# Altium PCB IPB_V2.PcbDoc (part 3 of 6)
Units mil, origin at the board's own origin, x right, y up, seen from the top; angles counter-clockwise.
Board outline 14000 x 12000 mil, 6 copper layers (Top, L2 - Plane/Horiz, L3 - Horiz, L4 - Vert, L5 - Plane/Horiz, Bottom), stack 61.468 mil thick; 657 components, 436 nets, 1897 pads, 873 vias.
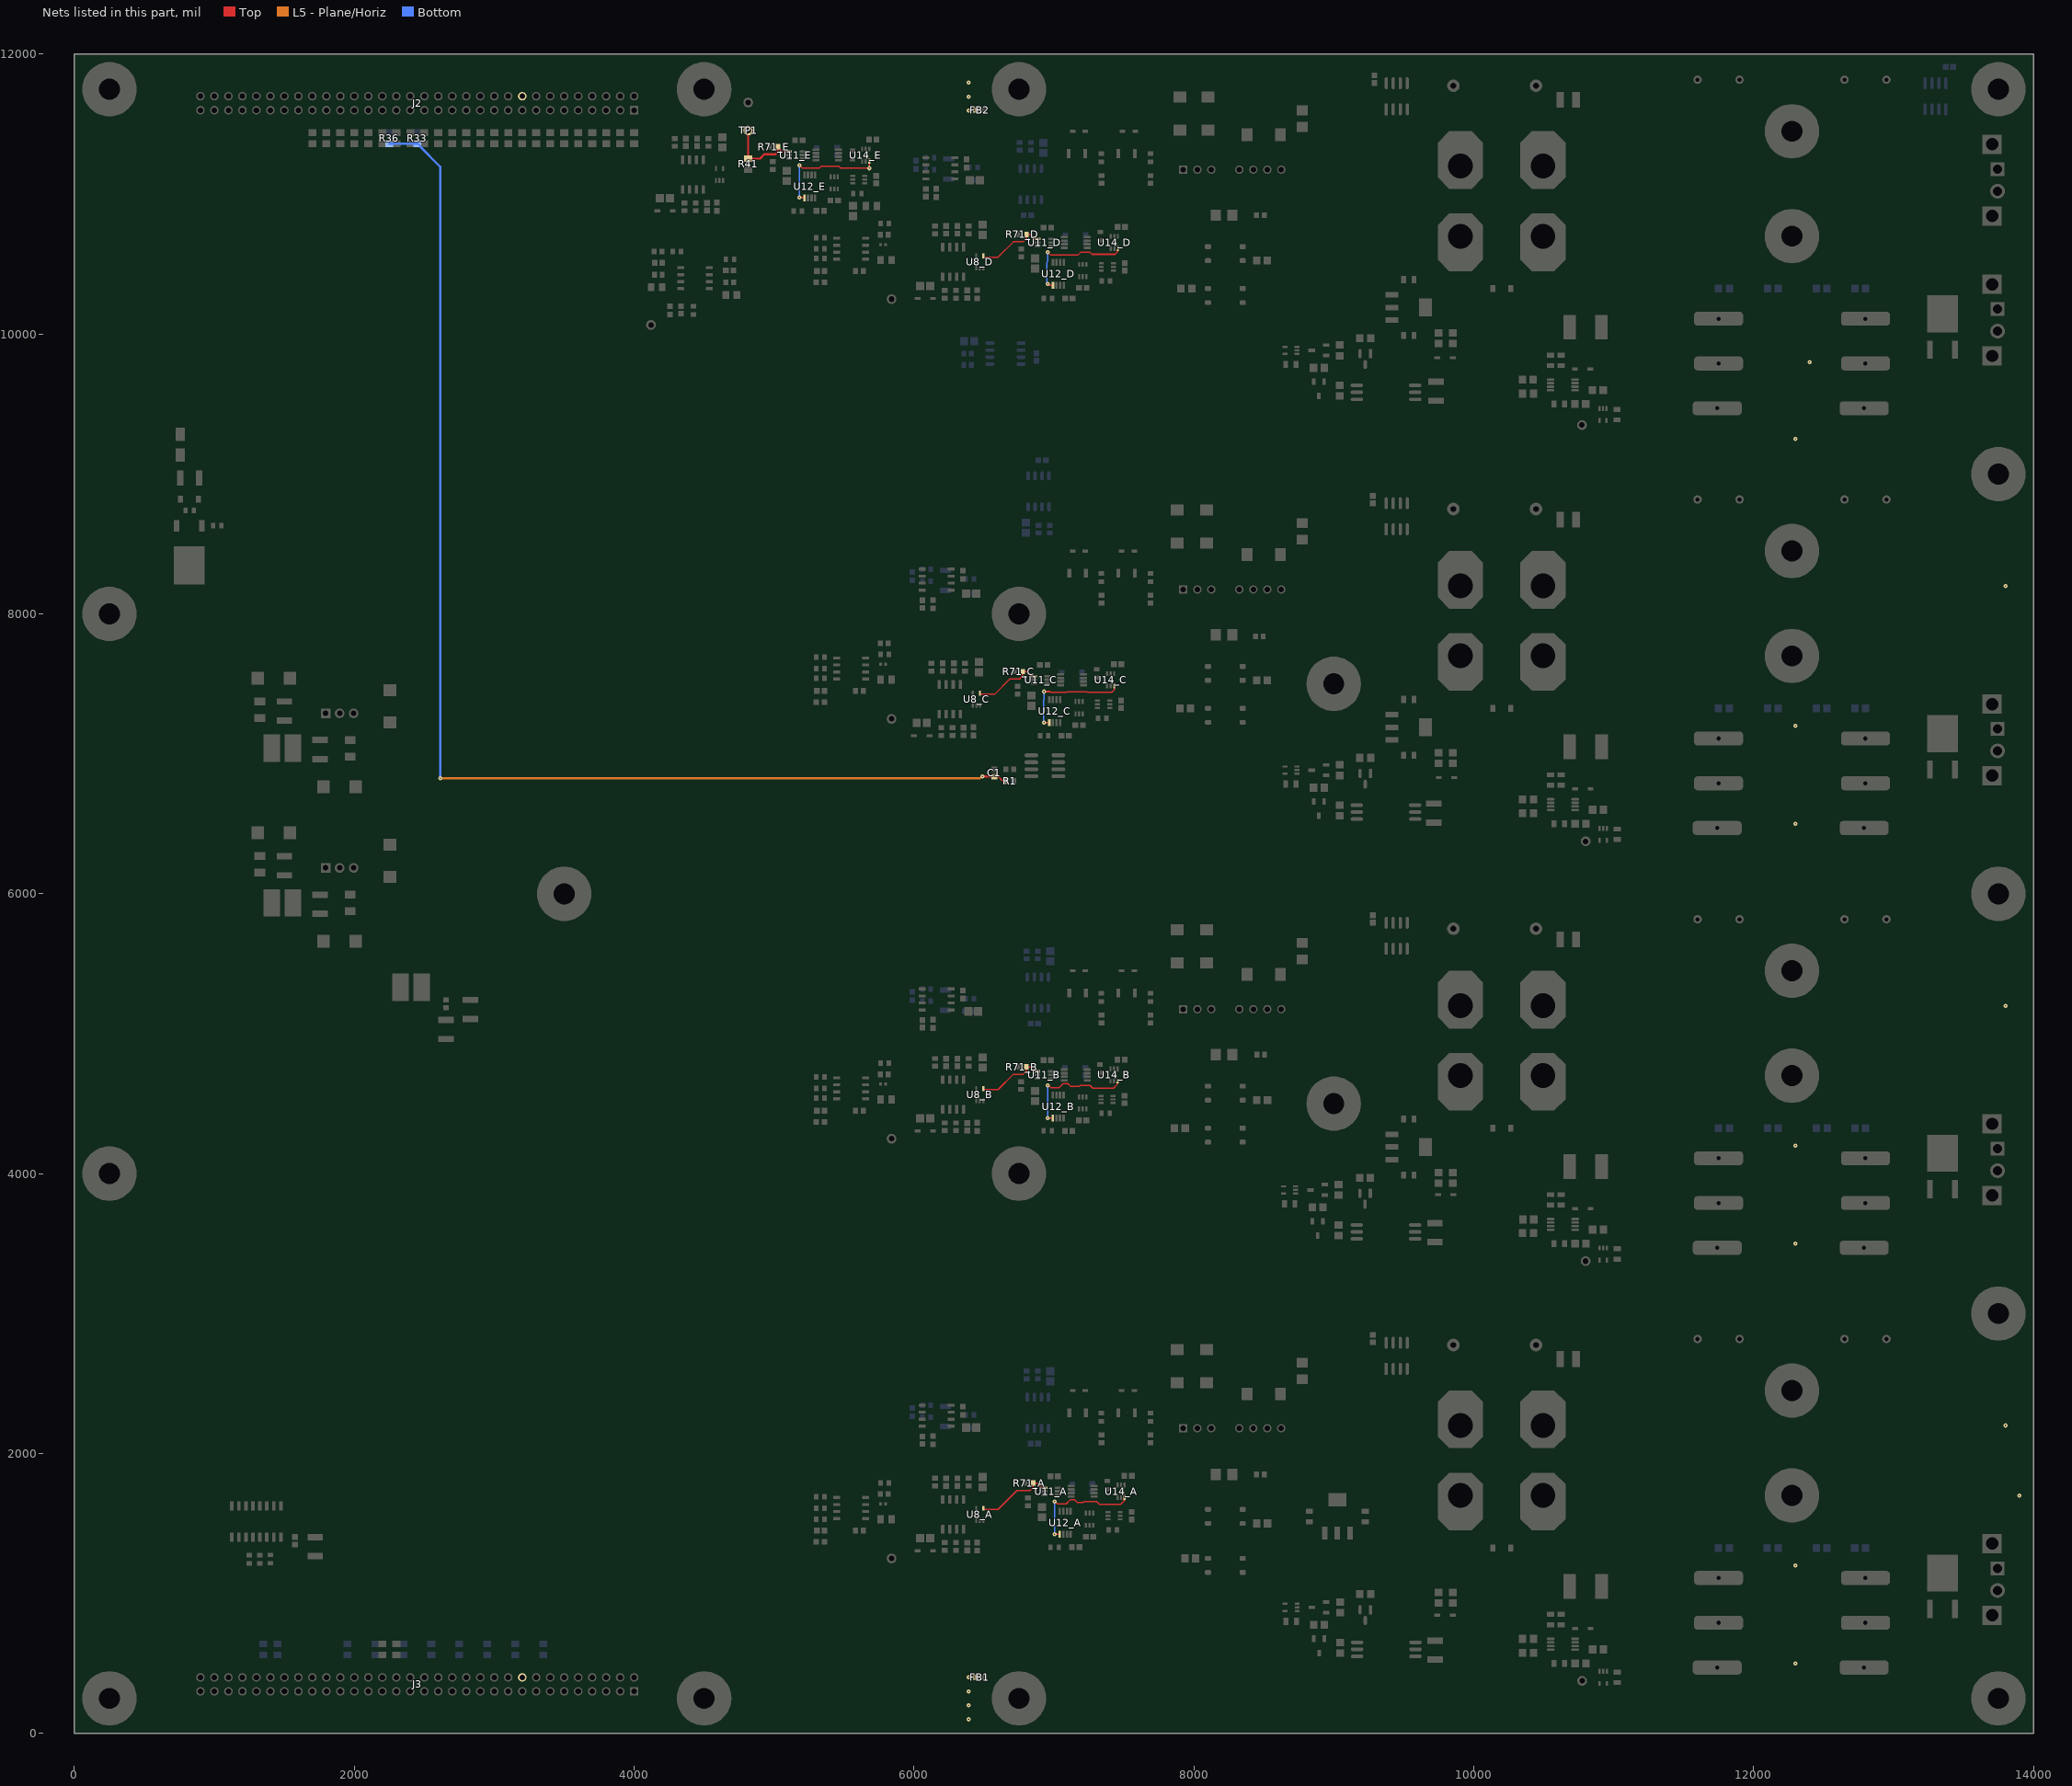
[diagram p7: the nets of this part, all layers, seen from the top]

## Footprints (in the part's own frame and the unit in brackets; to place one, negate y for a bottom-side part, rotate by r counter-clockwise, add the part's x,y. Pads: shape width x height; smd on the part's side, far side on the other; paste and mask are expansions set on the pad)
ADI-R-8_M [mm] "SOIC, 8-Leads, Body 4.9x3.9mm, Pitch 1.27mm, IPC Low Density"
  oval 2.5x0.7 smd: 1(-2.45,1.905) 2(-2.45,0.635) 3(-2.45,-0.635) 4(-2.45,-1.905) 5(2.45,-1.905) 6(2.45,-0.635) 7(2.45,0.635) 8(2.45,1.905)
  silkscreen extent -2.57,-2.5 0.8,2.93, body extent -2,-2.5 2,2.5, height 1.75
CAPC0402(1005)33_L [mm] "Chip Capacitor, Body 1.0x0.5mm, Height 0.33mm, IPC High Density"
  rrect25% 0.5x0.55 smd: 1(-0.45,0) 2(0.45,0)
  silkscreen extent 0,-0.2 0,0.2, body extent -0.5,-0.25 0.5,0.25, height 0.55
CAPC1608X90X40ML10T20 [mm] "Chip Capacitor, 2-Leads, Body 1.70x0.90mm, IPC Low Density"
  rect 1.05x1.05 smd: 1(-0.675,0) 2(0.675,0)
  body extent -0.85,-0.45 0.85,0.45, height 0.9
CAPC1608X94X35NL15T15 [mm] "Chip Capacitor, 2-Leads, Body 1.75x0.96mm, IPC Medium Density"
  rect 1.05x1 smd: 1(-0.75,0) 2(0.75,0)
  body extent -0.87,-0.48 0.87,0.48, height 0.94
CAPC2012X11M [mm] "Chip Capacitor, 2-Leads, Body 2.00x1.25mm, IPC Low Density"
  rect 1.5x1.55 smd: 1(-0.9,0) 2(0.9,0)
  body extent -1.1,-0.72 1.1,0.72, height 1.1
CAPC2013X95X50ML10T25 [mm] "Chip Capacitor, 2-Leads, Body 2.10x1.35mm, IPC Low Density"
  rect 1.45x1.5 smd: 1(-0.925,0) 2(0.925,0)
  body extent -1.05,-0.67 1.05,0.67, height 0.95
CAPC3225X270X30ML30 [mm] "Chip Capacitor, 2-Leads, Body 3.5x2.7mm, IPC Low Density"
  rect 1.15x2.8 smd: 1(-1.725,0) 2(1.725,0)
  silkscreen extent -0.75,-1.3 0.75,1.3, body extent -1.75,-1.35 1.75,1.35, height 2.7
CONV_RS3-2412S [mm]
  rect 1.508x1.508 hole 1: 1(-8.9,1.4)
  round 1.508 hole 1: 2(-6.36,1.4) 3(-3.82,1.4) 5(1.26,1.4) 6(3.8,1.4) 7(6.34,1.4) 8(8.88,1.4)
  silkscreen extent -11.9,-4.6 10.9,4.6, body extent -10.9,-4.6 10.9,4.6, height 11.1
D0008A_L [mm] "SOIC, 8-Leads, Body 5x4mm, Pitch 1.27mm, IPC High Density"
  rrect18% 1.25x0.55 smd: 1(-2.625,1.905) 2(-2.625,0.635) 3(-2.625,-0.635) 4(-2.625,-1.905) 5(2.625,-1.905) 6(2.625,-0.635) 7(2.625,0.635) 8(2.625,1.905)
  silkscreen extent -2.75,-2.5 1.6,2.85, body extent -3,-2.45 3,2.45, height 1.63
D0016A_M [mm] "SOIC, 16-Leads, Body 10x4mm, Pitch 1.27mm, IPC Low Density"
  rrect15% 1.65x0.65 smd: 1(-2.825,4.445) 2(-2.825,3.175) 3(-2.825,1.905) 4(-2.825,0.635) 5(-2.825,-0.635) 6(-2.825,-1.905) 7(-2.825,-3.175) 8(-2.825,-4.445) 9(2.825,-4.445) 10(2.825,-3.175) 11(2.825,-1.905) 12(2.825,-0.635) 13(2.825,0.635) 14(2.825,1.905) 15(2.825,3.175) 16(2.825,4.445)
  silkscreen extent -2.95,-5 1.6,5.45, body extent -3,-4.95 3,4.95, height 1.59
DCK0006A_M [mm] "SOT23, 6-Leads, Body 2.15x1.4mm, Pitch 0.65mm, IPC Low Density"
  rrect22% 1.05x0.45 smd: 1(-1.225,0.65) 2(-1.225,0) 3(-1.225,-0.65) 4(1.225,-0.65) 5(1.225,0) 6(1.225,0.65)
  silkscreen extent -1.35,-1.1 0.3,1.55, body extent -1.14,-1 1.14,1, height 0.94
DCT0008A_M [mm] "SOP, 8-Leads, Body 2.9x3.2mm, Pitch 0.65mm, IPC Low Density"
  rrect22% 1.25x0.45 smd: 1(-2.075,0.975) 2(-2.075,0.325) 3(-2.075,-0.325) 4(-2.075,-0.975) 5(2.075,-0.975) 6(2.075,-0.325) 7(2.075,0.325) 8(2.075,0.975)
  silkscreen extent -2.2,-1.6 1.05,1.87, body extent -2.01,-1.47 2.01,1.48, height 1.3
DIOM4326X11M [mm] "Molded Diode, 2-Leads, Body 4.30x2.60mm, IPC Low Density"
  rect 2.45x1.7 smd: 1(-1.875,0) 2(1.875,0)
  silkscreen extent -2.3,-1.4 3.07,1.53, body extent -2.52,-1.4 2.52,1.4, height 1.1
FAIR-SOD-323_V [mm] "SODFL, 2-Leads, Body 1.25x1.7mm"
  rect 1.05x0.55 smd: 1(-1.4,0) 2(1.4,0)
  silkscreen extent -0.85,-0.63 2.43,0.63, body extent -1.25,-0.63 1.25,0.63, height 1
FP-BLM18-0_15-t0_5-d1_2-IPC_B [mil]
  rect 43.55x37.73 smd paste+0 mask+0: 1(-26.62,0) 2(26.62,0)
  silkscreen extent -48,-35 48,35, body extent -58,-29 58,29, height 10
FP-C1206X102KGRACAUTO-IPC_A [mil]
  rect 70.97x80.85 smd paste+0 mask+0: 1(-59.06,0) 2(59.06,0)
  body extent -114,-60 114,60, height 10
FP-CGA5L-0_3-0_1-IPC_A [mm]
  rect 0.956x2.006 smd paste+0 mask+0: 1(-1.825,0) 2(1.825,0)
  silkscreen extent -1.05,-1 1.05,1, body extent -1.6,-0.76 1.6,0.84, height 1.9
FP-D0008A-IPC_B [mil]
  rect 85.4x22.92 smd paste+0 mask+0: 1(-93.06,75)
  rrect100% 85.4x22.92 smd paste+0 mask+0: 2(-93.06,25) 3(-93.06,-25) 4(-93.06,-75) 5(93.06,-75) 6(93.06,-25) 7(93.06,25) 8(93.06,75)
  silkscreen extent -162,-97 31,97, body extent -146,-106 146,106, height 10
FP-D0008A-MFG [mm] "SOIC, 8-Leads, Body 5x4mm, Pitch 1.27mm, IPC High Density"
  rrect17% 1.55x0.6 smd paste+0 mask+0: 1(-2.7,1.905) 2(-2.7,0.635) 3(-2.7,-0.635) 4(-2.7,-1.905) 5(2.7,-1.905) 6(2.7,-0.635) 7(2.7,0.635) 8(2.7,1.905)
  silkscreen extent -4.17,-2.5 1.5,2.5, body extent -3.57,-2.75 3.57,2.75, height 0.25
FP-DCK0005A-MFG [mm]
  rect 0.9x0.4 smd paste-1000 mask+0: 1(-1.1,0.65) 2(-1.1,0) 3(-1.1,-0.65) 4(1.1,-0.65) 5(1.1,0.65)
  silkscreen extent -2.22,-1.07 0.7,1.07, body extent -1.65,-1.33 1.65,1.33, height 0.25
FP-DCK0006A-MFG [mm]
  rect 0.9x0.4 smd paste-1000 mask+0: 1(-1.1,0.65) 2(-1.1,0) 3(-1.1,-0.65) 4(1.1,-0.65) 5(1.1,0) 6(1.1,0.65)
  silkscreen extent -2.22,-1.07 0.27,1.07, body extent -1.65,-1.33 1.65,1.33, height 0.25
FP-M80-5000000M5-02-333-0-MFG [mm]
  rect 2.5x2.5 hole 1.65 paste-2539.97 mask+0: A(2,1.8)
  round 2.667 hole 1.65 paste-2539.97 mask+0: B(-2,1.8)
  rect 3.5x3.5 hole 2.25 paste-2539.97 mask+0: MT1(-6.5,2.8) MT2(6.5,2.8)
  silkscreen extent -9.25,-4.4 9.25,5.2, body extent -9.35,-4.5 9.35,4.6, height 0.25
FP-SOT23-IPC_A [mm]
  rect 1.655x0.602 smd paste+0 mask+0: 1(-0.975,0.95)
  rrect100% 1.655x0.602 smd paste+0 mask+0: 2(-0.975,-0.95) 3(0.975,0)
  silkscreen extent 0,-1.45 0.65,1.45, body extent -2.3,-1.95 2.3,1.95, height 0.25
FP-T491X226K050AT-MFG [mm]
  rect 1.99x2.33 smd paste+0 mask+0: 1(-3.01,0) 2(3.01,0)
  silkscreen extent -3.8,-2.3 5.28,2.3, body extent -3.65,-2.15 3.65,2.15, height 4.3
G41C [mil] "5kV SPDT High Voltage Relay"
  rrect50% 350x100 hole 30 slot 200 at 0 deg: 1(0,390) 3(10,1030) 4(0,710)
  round 60 hole 30: 2(-150,-1318) 5(150,-1318)
  body extent -325,-1655 325,1109, height 690
INA310 [mm] "INA310 Current Sense Amp."
  oval 1.4x0.45 smd: 1(-2.225,0.975) 2(-2.225,0.325) 3(-2.225,-0.325) 4(-2.225,-0.975) 5(2.225,-0.975) 6(2.225,-0.325) 7(2.225,0.325) 8(2.225,0.975)
  silkscreen extent -2.35,-1.55 1.15,1.9, body extent -2.45,-1.55 2.45,1.55, height 1.1
INDP4848X30M [mm] "Precision Wire Wound Inductor, 2-Leads, Body 4.80x4.80mm, IPC Low Density"
  rect 3x5 smd: 1(-1.9,0) 2(1.9,0)
  body extent -2.4,-2.4 2.4,2.4, height 2.8
INF-PG-TO252-3-1_M [mm] "DPAK, 3-Leads, Body 6.525x6.12mm, Pitch 2.28mm, IPC Low Density"
  rect 2.05x1 smd: 1(-4.8,2.28) 3(-4.8,-2.28)
  rect 6.9x5.65 smd: 2(2.4,0)
  silkscreen extent -4.92,-3.35 -1.45,3.46, body extent -2.05,-3.32 4.17,3.32, height 2.35
IXFN66N85X-Footprint-1 [mil]
  oct 325x412.5 hole 177.2 copper offset 0,43.75: D(-295,250) S2(295,250)
  oct 325x412.5 hole 177.2 copper offset 0,-43.75: G(-295,-250) S1(295,-250)
  silkscreen extent -750,-525 750,525, body extent -749,-490 751,490, height 473
KEMT-D-7343-31-2_L [mm] "Molded TAN Capacitor, 2-Leads, Body 7.6x4.6mm, IPC High Density"
  rect 2.2x2.35 smd: 1(-2.925,0) 2(2.925,0)
  silkscreen extent -4.53,-2.3 3.8,2.3, body extent -3.8,-2.3 3.8,2.3, height 3.1
"Keystone 5001" [mil]
  round 70 hole 40: 1(0,0)
  silkscreen extent -55,-55 55,55, body extent -50,-50 50,50, height 180
"Keystone 5002" [mil]
  round 70 hole 40: 1(0,0)
  silkscreen extent -55,-55 55,55, body extent -50,-50 50,50, height 180
"MH-M3-Footprint-1 - Oversized MARS2" [mil] "Oversized specific for the MARS2 Project."
  round 390 / inner round 200 / far side round 390 hole 150: 1(0,0)
ONSC-SOD-123-2-425-04_V [mm] "SOD, 2-Leads, Body 2.69x1.6mm"
  rect 0.91x1.22 smd: 1(-1.635,0) 2(1.635,0)
  silkscreen extent -1.76,-0.8 0.78,1.28, body extent -1.35,-0.8 1.35,0.8, height 1.35
PANASONIC_ERJ6E [mm] "PANASONIC ERJ6E series 0805 resistors. /  / Chip Resistor, 2-Leads, Body 2.00x1.25mm, IPC Low Density"
  rect 1.35x1.45 smd: 1(-0.975,0) 2(0.975,0)
  body extent -1.1,-0.67 1.1,0.67, height 0.7
R76QI222050H4J-Footprint-1 [mil]
  round 90 hole 41.34: 1(-295.28,0) 2(295.28,0)
  silkscreen extent -375,-150 375,150, body extent -360,-122 360,122, height 476
REPO-R-78XX-3_V [mm] "Module, 3-Leads, Body 11.5x7.55mm, Pitch 2.54mm"
  rect 1.75x1.75 hole 1: 1(-2.54,0)
  round 1.75 hole 1: 2(0,0) 3(2.54,0)
  silkscreen extent -5.75,-2.77 5.75,5.55, body extent -5.75,-2 5.75,5.55, height 10.2
RESC1608X55X25ML10T15 [mm] "Chip Resistor, 2-Leads, Body 1.70x0.90mm, IPC Low Density"
  rect 0.8x1 smd: 1(-0.75,0) 2(0.75,0)
  body extent -0.85,-0.45 0.85,0.45, height 0.55
RESC1609X50X30ML08T20 [mm] "Chip Resistor, 2-Leads, Body 1.65x0.95mm, IPC Low Density"
  rect 0.9x1.05 smd: 1(-0.7,0) 2(0.7,0)
  body extent -0.82,-0.48 0.82,0.48, height 0.5
RESC2013X60X35ML10T20 [mm] "Chip Resistor, 2-Leads, Body 2.1x1.35mm, IPC Low Density"
  rect 1.2x1.45 smd: 1(-1,0) 2(1,0)
  silkscreen extent -0.1,-0.62 0.1,0.62, body extent -1.05,-0.68 1.05,0.67, height 0.6
RESC3115X07M [mm] "Chip Resistor, 2-Leads, Body 3.13x1.55mm, IPC Low Density"
  rect 1.4x1.95 smd: 1(-1.5,0) 2(1.5,0)
  silkscreen extent -0.4,-0.87 0.4,0.87, body extent -1.63,-0.72 1.63,0.72, height 0.7
RESC3126X06M [mm] "Chip Resistor, 2-Leads, Body 3.10x2.60mm, IPC Low Density"
  rect 1.4x2.85 smd: 1(-1.45,0) 2(1.45,0)
  silkscreen extent -0.35,-1.32 0.35,1.33, body extent -1.6,-1.38 1.6,1.38, height 0.65
RESC7142X88N [mm]
  rect 2.28x4.47 smd: 1(-2.895,0) 2(2.895,0)
  silkscreen extent -1.44,-2.1 1.44,2.1, body extent -3.56,-2.1 3.56,2.1, height 0.89
SMTC-ESQ-132-14-X-D [mm] "Elevated Socket, 2x32 Pins, Vertical, 2.54mm Pitch, Female"
  rect 1.55x1.55 hole 1.02: 1(0,0)
  round 1.55 hole 1.02: 2(0,-2.54) 3(2.54,0) 4(2.54,-2.54) 5(5.08,0) 6(5.08,-2.54) 7(7.62,0) 8(7.62,-2.54) 9(10.16,0) 10(10.16,-2.54) 11(12.7,0) 12(12.7,-2.54) 13(15.24,0) 14(15.24,-2.54) 15(17.78,0) 16(17.78,-2.54) 17(20.32,0) 18(20.32,-2.54) 19(22.86,0) 20(22.86,-2.54) 21(25.4,0) 22(25.4,-2.54) 23(27.94,0) 24(27.94,-2.54) 25(30.48,0) 26(30.48,-2.54) 27(33.02,0) 28(33.02,-2.54) 29(35.56,0) 30(35.56,-2.54) 31(38.1,0) 32(38.1,-2.54) 33(40.64,0) 34(40.64,-2.54) 35(43.18,0) 36(43.18,-2.54) 37(45.72,0) 38(45.72,-2.54) 39(48.26,0) 40(48.26,-2.54) 41(50.8,0) 42(50.8,-2.54) 43(53.34,0) 44(53.34,-2.54) 45(55.88,0) 46(55.88,-2.54) 47(58.42,0) 48(58.42,-2.54) 49(60.96,0) 50(60.96,-2.54) 51(63.5,0) 52(63.5,-2.54) 53(66.04,0) 54(66.04,-2.54) 55(68.58,0) 56(68.58,-2.54) 57(71.12,0) 58(71.12,-2.54) 59(73.66,0) 60(73.66,-2.54) 61(76.2,0) 62(76.2,-2.54) 63(78.74,0) 64(78.74,-2.54)
  silkscreen extent -1.53,-3.74 80.27,1.2, body extent -1.52,-3.81 80.26,1.27, height 11.05
SODFL250X80-2M [mm] "SODFL, 2-Leads, Body 1.25x2.50mm, IPC Low Density"
  rect 1x0.55 smd: 1(-1.15,0) 2(1.15,0)
  silkscreen extent -1.6,-0.7 0.9,0.7, body extent -1.25,-0.67 1.25,0.67, height 0.8
SOIC127P600X175-8M [mm] "SOIC, 8-Leads, Body 4.90x3.90mm, Pitch 1.27mm, IPC Low Density"
  oval 1.65x0.65 smd: 1(-2.825,1.905) 2(-2.825,0.635) 3(-2.825,-0.635) 4(-2.825,-1.905) 5(2.825,-1.905) 6(2.825,-0.635) 7(2.825,0.635) 8(2.825,1.905)
  silkscreen extent -2.95,-2.5 1.6,2.91, body extent -3,-2.5 3,2.5, height 1.75
SOIC127P1150X355-6M [mm] "SOIC, 6-Leads, Body 4.68x7.50mm, Pitch 1.27mm, IPC Low Density"
  oval 2.25x0.65 smd: 1(-5.3,1.27) 2(-5.3,0) 3(-5.3,-1.27) 4(5.3,-1.27) 5(5.3,0) 6(5.3,1.27)
  silkscreen extent -5.42,-2.4 3.78,2.4, body extent -5.75,-2.4 5.75,2.4, height 3.55
SOT89-150P341X160-3M [mm] "SOT89, 3-Leads, Body 4.50x2.45mm, Pitch 1.50mm, Lead Span 3.4mm, IPC Low Density"
  rect 1.6x0.7 smd: 1(-1.65,1.5) 3(-1.65,-1.5)
  round 0.025 smd: 2(-1.7,0)
  Top region: -0.95,0.35 -0.3,1 -0.3,1 1.8,1 2.45,0.35 2.45,-0.35 1.8,-1 -0.3,-1 -0.95,-0.35 -2.45,-0.35 -2.45,0.35
  silkscreen extent -1.93,-2.3 1.45,2.53, body extent -2.2,-2.3 1.85,2.3, height 1.6
SOT95P237X111-3M [mm] "SOT23, 3-Leads, Body 2.92x2.37mm, Pitch 0.95mm, IPC Low Density"
  rect 1.2x0.65 smd: 1(-1.3,0.95) 2(-1.3,-0.95) 3(1.3,0)
  silkscreen extent -1.42,-1.5 0.7,1.95, body extent -1.32,-1.52 1.32,1.52, height 1.11
SOT230P700X180-4M [mm] "SOT223, 4-Leads, Body 6.50x7.00mm (avg), Pitch 2.30mm, IPC Low Density"
  rect 2.35x1 smd: 1(-3.025,2.3) 2(-3.025,0) 3(-3.025,-2.3)
  rect 2.35x3.25 smd: 4(3.025,0)
  silkscreen extent -3.15,-3.35 1.4,3.47, body extent -3.5,-3.35 3.5,3.35, height 1.8
TO-252AA-IPC_A-APL [mm] "IPC Level A, Low-Density, DPAK. Created via JEDEC TO-252 dimensions and Altium IPC wizard."
  rect 3.3x1.05 smd: 1(-4.1,2.29) 3(-4.1,-2.29)
  rect 6.7x5.6 smd: 4(2.4,0)
  silkscreen extent -4.22,-3.35 -1.35,3.49, body extent -4.29,-3.37 5.61,3.37, height 2.52
WCAP-CSGP_0805_L2W1.25H0.8_Reflow [mm] "Ceramic Capacitors, body 2x1.25mm"
  rect 0.9x1.3 smd: 1(-0.95,0) 2(0.95,0)
  body extent -1,-0.62 1,0.63, height 0.8
WCAP-CSGP_0805_L2W1.25H1.25 [mm] "Ceramic Capacitors, body 2x1.25mm"
  rect 0.9x1.3 smd: 1(-0.95,0) 2(0.95,0)
  body extent -1,-0.63 1,0.63, height 1.25
WL-OCPT_SOP4 [mm] "Optocoupler Phototransistor, body 4.4x3.6mm"
  rrect50% 1.1x0.9 smd: 1(-3.15,1.27) 2(-3.15,-1.27) 3(3.15,-1.27) 4(3.15,1.27)
  silkscreen extent -3.27,-1.9 2.3,2.37, body extent -3.5,-1.8 3.5,1.8, height 2.1

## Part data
C1 C10_A C10_B C10_C C10_D C10_E C12 C29_A C29_B C29_C C29_D C29_E C30_A C30_B C30_C C30_D C30_E C31_A C31_B C31_C C31_D C31_E C32_A C32_B C32_C C32_D C32_E C34_A C34_B C34_C C34_D C34_E C35_A C35_B C35_C C35_D C35_E C57_A C57_B C57_C C57_D C57_E: library part CMP-001-00206-10, "Chip Capacitor, 100nF, +/- 10%, 50 V, X7R 0603 (1608 Metric)", Capacitance=100nF, Capacitor Type=Ceramic, Case/Package=0603, Dielectric=X7R, Max Operating Temperature=125°C, Min Operating Temperature=-55°C, Tolerance=10%, Voltage Rating=50V
C2 C25_A C25_B C25_C C25_D C25_E C27_A C27_B C27_C C27_D C27_E C28_A C28_B C28_C C28_D C28_E: library part CMP-001-00018-16, "Chip Capacitor, 100 nF, +/- 10%, 50 V, 0805 (2012 Metric)", Capacitance=100nF, Capacitor Type=Ceramic, Case/Package=0805, Max Operating Temperature=125°C, Min Operating Temperature=-55°C, Tolerance=10%, Voltage Rating=50V
C3 C6 C24_A C24_B C24_C C24_D C24_E C26_A C26_B C26_C C26_D C26_E: library part CMP-001-00153-10, "Chip Capacitor, 1nF, +/- 5%, 50 V, C0G 0603 (1608 Metric)", Capacitance=1nF, Capacitor Type=Ceramic, Case/Package=0603, Dielectric="C0G, NPO", Max Operating Temperature=125°C, Min Operating Temperature=-55°C, Tolerance=5%, Voltage Rating=50V
C4 C7_A C7_B C7_C C7_D C22_A C22_B C22_C C22_D C22_E C36_A C36_B C36_C C36_D: library part CMP-001-00166-10, "Chip Capacitor, 10nF, +/- 5%, 50 V, C0G 0603 (1608 Metric)", Capacitance=10nF, Capacitor Type=Ceramic, Case/Package=0603, Dielectric="C0G, NPO", Max Operating Temperature=125°C, Min Operating Temperature=-55°C, Tolerance=5%, Voltage Rating=50V
C5 C8_A C8_B C8_C C8_D C23_A C23_B C23_C C23_D C23_E C37_A C37_B C37_C C37_D C40_A C40_B C40_C C40_D C41_A C41_B C41_C C41_D: library part CMP-001-00003-15, "Chip Capacitor, 1 uF, +/- 10%, 16 V, 0603 (1608 Metric)", Capacitance=1µF, Capacitor Type=Ceramic, Case/Package=0603, Max Operating Temperature=125°C, Min Operating Temperature=-55°C, Tolerance=10%, Voltage Rating=16V
C9_A C9_B C9_C C9_D: library part CMP-001-00066-11, "Chip Capacitor, 1nF +/-20%, 50V, 0402, Thickness 0.33 mm", Capacitance=1nF, Capacitor Type=Ceramic, Case/Package=0402, Max Operating Temperature=85°C, Min Operating Temperature=-55°C, Tolerance=10%, Voltage Rating=50V
C11 C14: library part CMP-001-00181-10, "Chip Capacitor, 1uF, 10%, 50 V, X7R 1210 (3225 Metric)", Capacitance=1uF, Capacitor Type=Ceramic, Case/Package=1210, Dielectric=X7R, Max Operating Temperature=125°C, Min Operating Temperature=-55°C, Tolerance=10%, Voltage Rating=50V
C13 C15 C45 C46 C55 C56: library part CMP-001-00183-10, "Chip Capacitor, 4.7uF, 10%, 50 V, X7R 1210 (3225 Metric)", Capacitance=4.7uF, Capacitor Type=Ceramic, Case/Package=1210, Dielectric=X7R, Max Operating Temperature=125°C, Min Operating Temperature=-55°C, Tolerance=10%, Voltage Rating=50V
C16_A C16_B C16_C C16_D C20_A C20_B C20_C C20_D: library part CMP-001-00212-10, "Cap Ceramic 0.001uF 2000V X7R 10% Pad SMD 1206 Flexible Termination 125C Low ESR Automotive T/R", Capacitance=1nF, Case/Package=1206, Dielectric=X7R, Manufacturer=KEMET, Max Operating Temperature=125°C, Min Operating Temperature=-55°C, Tolerance=10%, Voltage Rating=2kV
C17_A C17_B C17_C C17_D C18_A C18_B C18_C C18_D C19_A C19_B C19_C C19_D: library part CMP-001-00083-12, "Cap Tant Solid 22uF 50V X CASE 10% (7.3 X 4.3 X 4mm) SMD 7343-43 0.6 Ohm 125 C T/R", Capacitance=22uF, Case/Package=2917, ESR (Equivalent Series Resistance)=600mR, Manufacturer=KEMET, Max Operating Temperature=125°C, Min Operating Temperature=-55°C, Tolerance=10%, Voltage Rating=50V
C21_A C21_B C21_C C21_D: library part CMP-001-00184-10, "Chip Capacitor, 10uF, 10%, 50 V, X7R 1210 (3225 Metric)", Capacitance=10uF, Capacitor Type=Ceramic, Case/Package=1210, Dielectric=X7R, Max Operating Temperature=125°C, Min Operating Temperature=-55°C, Tolerance=10%, Voltage Rating=50V
C33_A C33_B C33_C C33_D C47_A C47_B C47_C C47_D: library part CMP-118-000238-3, "WCAP-CSGP Multilayer Ceramic Chip Capacitor, General Purpose, size 0805, X5R, 2.2uF, 25VDC", Capacitance=2.2uF, Capacitance Tolerance=+/-20%, Case/Size Code=0805, Insulation Resistance=0.05GOhm, Manufacturer="Wurth Elektronik", Operating Temperature Max=85°C, Operating Temperature Min=-55°C, Rated Voltage (DC)=25V
C38_A C38_B C38_C C38_D: library part CMP-001-00094-9, "Cap Ceramic 6.8uF 25V X7R 10% SMD 1206 125°C Blister Plastic T/R", Capacitance=6.8uF, Case/Package=1206, Dielectric=X7R, Manufacturer=TDK, Max Operating Temperature=125°C, Min Operating Temperature=-55°C, Tolerance=10%, Voltage Rating=25V
C39_A C39_B C39_C C39_D: library part CMP-001-00093-9, "Cap Ceramic 1.2uF 10V X7R 10% SMD 0805 125°C Plastic T/R", Capacitance=1.2uF, Case/Package=0805, Dielectric=X7R, Manufacturer=KEMET, Max Operating Temperature=125°C, Min Operating Temperature=-55°C, Tolerance=10%, Voltage Rating (DC)=10V
C42 C43 C44 C52 C53 C54: library part CMP-001-00088-10, "10uF Solid MnO2 Tantalum Electrolytic Capacitor; 50 V dc +/-10%; T491 Series", Capacitance=10uF, Case/Package=2917, Dielectric Material=Tantalum, ESR (Equivalent Series Resistance)=800mR, Leakage Current=5uA, Manufacturer=KEMET, Max Operating Temperature=125°C, Min Operating Temperature=-55°C, Package Quantity=20, Ripple Current=433mA, Tolerance=10%, Voltage=50V
C48_A C48_B C48_C C48_D C49_A C49_B C49_C C49_D C51_A C51_B C51_C C51_D C61_A C61_B C61_C C61_D: library part CMP-118-000468-2, "WCAP-CSGP Multilayer Ceramic Chip Capacitor, General Purpose, size 0805, X7R, 100nF, 25VDC", Capacitance=100nF, Capacitance Tolerance=+/-10%, Case/Size Code=0805, Insulation Resistance=5GOhm, Manufacturer="Wurth Elektronik", Operating Temperature Max=125°C, Operating Temperature Min=-55°C, Rated Voltage (DC)=25V
C50_A C50_B C50_C C50_D: library part CMP-118-000237-3, "WCAP-CSGP Multilayer Ceramic Chip Capacitor, General Purpose, size 0805, X5R, 1uF, 25VDC", Capacitance=1uF, Capacitance Tolerance=+/-20%, Case/Size Code=0805, Insulation Resistance=0.5GOhm, Manufacturer="Wurth Elektronik", Operating Temperature Max=85°C, Operating Temperature Min=-55°C, Rated Voltage (DC)=25V
C58_A C58_B C58_C C58_D C58_E: library part CMP-001-00165-11, "Chip Capacitor, 1uF, 10%, 50 V, X7R 0805 (2012 Metric)", Capacitance=1uF, Capacitor Type=Ceramic, Case/Package=0805, Dielectric=X7R, Max Operating Temperature=125°C, Min Operating Temperature=-55°C, Tolerance=10%, Voltage Rating=50V
C59_A C59_B C59_C C59_D: library part CMP-001-00247-2, "Double Metallized Polypropylene Film Capacitor", Capacitor Type=Film, Case/Package=Radial, Dielectric=PP, Max Operating Temperature=125°C, Min Operating Temperature=-55°C, Ratings=AEC-Q200, Tolerance=5%, Voltage Rating=1kV, Voltage Rating (AC)=600V
D1_A D1_B D1_C D1_D: library part CMP-004-00082-5, "Rectifier Diode, 1 Phase, 1 Element, 8A, 1600V V(RRM), Silicon, TO-252AA", Case/Package=TO-252AA, Maximum Operating Temperature=150C, Minimum Operating Temperature=-40C
D2: library part CMP-004-00041-1, "Diode Schottky Barrier Rectifier 200V 3A 2-Pin SMA-FL T/R", Average Rectified Current=3A, Max Reverse Voltage (DC)=200V
D3 D6_A D6_B D6_C D6_D: library part CMP-004-00039-2, "Diode Zener Single 15V 5% 500mW Automotive 2-Pin SOD-123 T/R", Case/Package=SOD-123-2, Max Operating Temperature=150°C, Max Power Dissipation=500mW, Max Reverse Leakage Current=50nA, Min Operating Temperature=-55°C, Zener Voltage=15V
D4_A D4_B D4_C D4_D D4_E D4_F D4_G D4_H: library part CMP-004-00035-1, "NXP         PMEG4010CEJ,115            Schottky Rectifier, Single, 40 V, 1 A, SOD-323F, 2 Pins, 570 mV", Case/Package=SOD-323F, Forward Current=1A, Max Forward Surge Current (Ifsm)=10A, Max Operating Temperature=150°C, Max Power Dissipation=830mW, Max Reverse Current=50uA, Max Reverse Voltage (DC)=40V, Min Operating Temperature=-65°C
D5_A D5_B D5_C D5_D D5_E D7_A D7_B D7_C D7_D D8_A D8_B D8_C D8_D: library part CMP-004-00001-3, "Small Signal Diode, 75 V, 0.15 A, -55 to 150 degC, 2-Pin SOD-323, RoHS, Tape and Reel", Capacitance=-323f, Case/Package=SOD-323, Forward Current=150mA, Forward Voltage=1V, Manufacturer=Fairchild, Max Operating Temperature=150°C, Min Operating Temperature=-55°C, Package Description="2-Pin Small Outline Diode Flat Lead, Body 1.7 x 1.25 mm", Package Quantity=3000, Peak Reverse Current=5uA
FB1 FB2: library part CMP-00000-2, "Ferrite Beads Multi-Layer 120Ohm 25% 100MHz 3A 0.025Ohm DCR 0603 T/R", Case/Package=0603, Current Rating=3A, DC Resistance (DCR)=25mR, Frequency=100MHz, Max Operating Temperature=125°C, Min Operating Temperature=-55°C, Package Quantity=1, Tolerance=25%
J1 J4 J5 J6 J7: library part CMP-002-00075-7, "Conn Header R/a 2POS 4MM", Color=Black, Contact Resistance=25mR, Current Rating=40A, Insulation Resistance=100MR, Manufacturer=Harwin, Max Operating Temperature=125°C, Maximum Voltage=800V, Min Operating Temperature=-55°C
J2 J3: library part CMP-002-00093-5, "Conn Elevated Socket SKT 64 POS 2.54mm Solder ST Top Entry Thru-Hole Tube", Color=Black, Contact Resistance=10mR, Current Rating=6.9A, Manufacturer=Samtec, Max Operating Temperature=125°C, Max Voltage Rating (AC)=550V, Min Operating Temperature=-55°C, Package Quantity=1
K1_A K1_B K1_C K1_D K2_A K2_B K2_C K2_D: library part CMP-008-00006-7, "5kV SPDT High Voltage Relay"
L1 L2 L4: library part CMP-006-00041-3, "Inductor Power Shielded Wirewound 18uH 30% 11.64 Q-Factor Ferrite 0.75A Saturation 160mROhm DCR", Current Rating=0.98A, DC Resistance (DCR)=160mR, Inductance=18uH, Inductance Tolerance=30%, Manufacturer=Bourns, Max Operating Temperature=125°C, Min Operating Temperature=-40°C, Saturation Current=0.75A, Self Resonant Frequency=25MHz
MH1 MH2 MH3 MH4 MH5 MH6 MH7 MH8 MH9 MH10 MH11 MH13 MH14 MH15 MH16 MH17 MH18 MH19 MH20 MH21 MH23 MH25 MH26 MH27 MH28 MH29: library part CMP-00028-00015-2, "MARS2 Project 6-32 Mounting Hole Plated ."
PS1_A PS1_B PS1_C PS1_D: library part CMP-167-000000-3, "3W DC/DC-Converter 'ECONOLINE' SIP8 1kV reg 2:1", Isolation Voltage=1kV, Manufacturer="Recom Power", Max Output Current=250mA, Maximum Input Voltage=36V, Maximum Operating Temperature=71C, Minimum Input Voltage=18V, Minimum Operating Temperature=-40C, Package="SIP-8 Recom Power"
Q1: library part CMP-013-00049-3, "Trans MOSFET P-CH 100V 4A Automotive 3-Pin(2+Tab) TO-252 T/R", Case/Package=TO-252-3, Continuous Drain Current (ID)=4A, Drain to Source Breakdown Voltage=-100V, Gate to Source Voltage (Vgs)=20V, Input Capacitance=319pF, Max Operating Temperature=175°C, Min Operating Temperature=-55°C, Power Dissipation=38W
Q2_A Q2_B Q2_C Q2_D Q2_E Q2_F Q2_G Q2_H: library part CMP-013-00045-4, "Transistor MOSFET N-CH 40V 0.89A 4-Pin (3+Tab) SOT-89", Case/Package=SOT-89-3, Continuous Drain Current (ID)=890mA, Drain to Source Breakdown Voltage=40V, Gate to Source Voltage (Vgs)=20V, Max Operating Temperature=150°C, Max Power Dissipation=1.6W, Min Operating Temperature=-55°C
Q3_A Q3_B Q3_C Q3_D: library part CMP-013-00040-7, "Trans MOSFET N-CH 850V 65A 4-Pin SOT-227B", Case/Package=SOT-227B, Current=65A, Voltage=850V
Q4_A Q4_B Q4_C Q4_D Q8_A Q8_B Q8_C Q8_D: library part CMP-00026-00003-3, "Optocoupler, Transistor, 35V, Sop-4 Rohs Compliant: Yes", Case/Package="SOP 4"
Q5_A Q5_B Q5_C Q5_D: library part CMP-013-00003-8, "PNP General-Purpose Amplifier, 40 V, 0.2 A, -55 to 150 degC, 3-Pin SOT23, RoHS, Tape and Reel", Case/Package=SOT-23-3, Collector Base Voltage (VCBO)=40V, Collector Emitter Saturation Voltage=-400mV, Collector Emitter Voltage (VCEO)=-40V, Collector-emitter Voltage-Max=400mV, Current Rating=-200mA, Emitter Base Voltage (VEBO)=5V, Frequency=250MHz, Manufacturer="ON Semiconductor", Max Collector Current=200mA, Max Operating Temperature=150°C, Max Power Dissipation=300mW, Min Operating Temperature=-55°C, Package Description="3-Pin Small Outline Transistor, Body 2.9 x 1.3 mm, Pitch 0.95 mm", Package Quantity=3000, Package Reference="SOT-23 (318-08)", Power=225mW
Q6_A Q6_B Q6_C Q6_D: library part CMP-013-00062-2, "BSS138P Series 60 V 1.6 Ohm 350 mW 0.72 nC N-Channel SMT TrenchMOS FET - SOT-23", Case/Package=SOT-23, Continuous Drain Current (ID)=360mA, Drain to Source Breakdown Voltage=60V, Drain to Source Resistance=900mR, Gate to Source Voltage (Vgs)=20V
Q7_A Q7_B Q7_C Q7_D: library part CMP-013-00007-8, "General Purpose Transistor, NPN Silicon, 40 V, 0.2 A, -55 to 150 degC, 3-Pin SOT23, RoHS, Tape and Reel", Case/Package=SOT-23, Collector Base Voltage (VCBO)=60V, Collector Emitter Breakdown Voltage=40V, Collector Emitter Saturation Voltage=300mV, Current Rating=200mA, Frequency=300MHz, Manufacturer="ON Semiconductor", Max Operating Temperature=150°C, Min Operating Temperature=-55°C, Package Description="3-Pin Small Outline Transistor, Body 2.9 x 1.3 mm, Pitch 0.95 mm", Package Quantity=3000, Power=225mW
R1: library part CMP-009-01135-2, "Chip Resistor, 51.1 Ohm, +/- 1%, 0.1 W, -55 to 155 degC, 0603 (1608 Metric)", Case/Package=0603, Max Operating Temperature=155°C, Min Operating Temperature=-55°C, Power=100mW, Tolerance=1%, Voltage Rating=75V
R2: library part CMP-009-00865-5, "Chip Resistor, 7.15k Ohm, +/- 1%, 0.1 W, -55 to 155 degC, 0603 (1608 Metric)", Case/Package=0603, Max Operating Temperature=155°C, Min Operating Temperature=-55°C, Power=100mW, Tolerance=1%, Voltage Rating=75V
R3 R4 R5 R6 R7 R8 R9 R10 R11 R12 R13 R14 R15 R16 R17 R18 R19 R20 R21 R22 R23 R24 R25 R26 R27 R28 R29 R30 R31 R32 R33 R34 R35 R36 R37 R38 R39 R40 R41 R42 R45 R49 R53_A R53_B R53_C R53_D: library part CMP-009-00007-7, "Chip Resistor, 0 Ohm, 0.125 W, -55 to 155 degC, 0805 (2012 Metric)", Case/Package=0805, Max Operating Temperature=155°C, Min Operating Temperature=-55°C, Power=125mW, Tolerance=5%, Voltage Rating=50V
R43: library part CMP-009-00871-5, "Chip Resistor, 8.25k Ohm, +/- 1%, 0.1 W, -55 to 155 degC, 0603 (1608 Metric)", Case/Package=0603, Max Operating Temperature=155°C, Min Operating Temperature=-55°C, Power=100mW, Tolerance=1%, Voltage Rating=75V
R44 R50 R52_A R52_B R52_C R52_D R55_A R55_B R55_C R55_D R56_A R56_B R56_C R56_D R57_A R57_B R57_C R57_D R65_A R65_B R65_C R65_D R65_E R65_F R65_G R65_H: library part CMP-009-00017-8, "Chip Resistor, 10 KOhm, +/- 1%, 01 W, -55 to 155 degC, 0603 (1608 Metric)", Case/Package=0603, Max Operating Temperature=155°C, Min Operating Temperature=-55°C, Power=100mW, Tolerance=1%, Voltage Rating=50V
R46: library part CMP-009-00997-4, "Chip Resistor, 45.3k Ohm, +/- 1%, 0.1 W, -55 to 155 degC, 0603 (1608 Metric)", Case/Package=0603, Max Operating Temperature=155°C, Min Operating Temperature=-55°C, Power=100mW, Tolerance=1%, Voltage Rating=75V
R47: library part CMP-009-00822-5, "Chip Resistor, 2.49k Ohm, +/- 1%, 0.1 W, -55 to 155 degC, 0603 (1608 Metric)", Case/Package=0603, Max Operating Temperature=155°C, Min Operating Temperature=-55°C, Power=100mW, Tolerance=1%, Voltage Rating=75V
R48: library part CMP-009-00834-5, "Chip Resistor, 3.32k Ohm, +/- 1%, 0.1 W, -55 to 155 degC, 0603 (1608 Metric)", Case/Package=0603, Max Operating Temperature=155°C, Min Operating Temperature=-55°C, Power=100mW, Tolerance=1%, Voltage Rating=75V
R51_A R51_B R51_C R51_D: library part CMP-009-00846-5, "Chip Resistor, 4.53k Ohm, +/- 1%, 0.1 W, -55 to 155 degC, 0603 (1608 Metric)", Case/Package=0603, Max Operating Temperature=155°C, Min Operating Temperature=-55°C, Power=100mW, Tolerance=1%, Voltage Rating=75V
R54_A R54_B R54_C R54_D: library part CMP-009-00872-5, "Chip Resistor, 8.45k Ohm, +/- 1%, 0.1 W, -55 to 155 degC, 0603 (1608 Metric)", Case/Package=0603, Max Operating Temperature=155°C, Min Operating Temperature=-55°C, Power=100mW, Tolerance=1%, Voltage Rating=75V
R58 R60 R70_A R70_B R70_C R70_D R70_E R71_A R71_B R71_C R71_D R71_E R73_A R73_B R73_C R73_D R73_E R74_A R74_B R74_C R74_D R74_E R75_A R75_B R75_C R75_D R75_E: library part CMP-009-01001-4, "Chip Resistor, 49.9k Ohm, +/- 1%, 0.1 W, -55 to 155 degC, 0603 (1608 Metric)", Case/Package=0603, Max Operating Temperature=155°C, Min Operating Temperature=-55°C, Power=100mW, Tolerance=1%, Voltage Rating=75V
R59: library part CMP-009-01177-2, "Chip Resistor, 3.9 Ohm, +/- 1%, 0.1 W, -55 to 155 degC, 0603 (1608 Metric)", Case/Package=0603, Max Operating Temperature=155°C, Min Operating Temperature=-55°C, Power=100mW, Tolerance=1%, Voltage Rating="SEE DATASHEET"
R61_A R61_B R61_C R61_D: library part CMP-009-00827-5, "Chip Resistor, 2.8k Ohm, +/- 1%, 0.1 W, -55 to 155 degC, 0603 (1608 Metric)", Case/Package=0603, Max Operating Temperature=155°C, Min Operating Temperature=-55°C, Power=100mW, Tolerance=1%, Voltage Rating=75V
R62_A R62_B R62_C R62_D R84_A R84_B R84_C R84_D R92_A R92_B R92_C R92_D R93_A R93_B R93_C R93_D: library part CMP-009-01342-2, "Generic 1% 4.99 kOhm 0805 Resistor", Case/Package=0805, Max Operating Temperature=+155C, Min Operating Temperature=-55C, Power=0.125W, Tolerance=1%, Voltage Rating=150V
R63_A R63_B R63_C R63_D R83_A R83_B R83_C R83_D: library part CMP-009-01863-3, "Generic 1% 768 Ohm 0805 Resistor", Case/Package=0805, Max Operating Temperature=+155C, Min Operating Temperature=-55C, Power=0.125W, Tolerance=1%, Voltage Rating=150V
R64_A R64_B R64_C R64_D R64_E R64_F R64_G R64_H: library part CMP-009-00745-5, "Chip Resistor, 348 Ohm, +/- 1%, 0.1 W, -55 to 155 degC, 0603 (1608 Metric)", Case/Package=0603, Max Operating Temperature=155°C, Min Operating Temperature=-55°C, Power=100mW, Tolerance=1%, Voltage Rating=75V
R66_A R66_B R66_C R66_D R66_E R69_A R69_B R69_C R69_D R69_E: library part CMP-009-00807-5, "Chip Resistor, 1.65k Ohm, +/- 1%, 0.1 W, -55 to 155 degC, 0603 (1608 Metric)", Case/Package=0603, Max Operating Temperature=155°C, Min Operating Temperature=-55°C, Power=100mW, Tolerance=1%, Voltage Rating=75V
R67_A R67_B R67_C R67_D R67_E: library part CMP-009-00760-5, "Chip Resistor, 499 Ohm, +/- 1%, 0.1 W, -55 to 155 degC, 0603 (1608 Metric)", Case/Package=0603, Max Operating Temperature=155°C, Min Operating Temperature=-55°C, Power=100mW, Tolerance=1%, Voltage Rating=75V
R68_A R68_B R68_C R68_D R68_E R72_A R72_B R72_C R72_D R72_E: library part CMP-009-00592-3, "Chip Resistor, 332K Ohm, +/- 1%, 100 mW, -55 to 155 degC, 0603 (1608 Metric)", Case/Package=0603, Max Operating Temperature=155°C, Min Operating Temperature=-55°C, Power=100mW, Tolerance=1%, Voltage Rating=75V
R76_A R76_B R76_C R76_D: library part CMP-009-01813-4, "Generic 1% 294 Ohm 0805 Resistor", Case/Package=0805, Max Operating Temperature=+155C, Min Operating Temperature=-55C, Power=0.125W, Tolerance=1%, Voltage Rating=150V
R77_A R77_B R77_C R77_D: library part CMP-009-00692-4, "Chip Resistor, 953 Ohm, +/- 1%, 0.1 W, -55 to 155 degC, 0603 (1608 Metric)", Case/Package=0603, Max Operating Temperature=155°C, Min Operating Temperature=-55°C, Power=100mW, Tolerance=1%, Voltage Rating=75V
R78_A R78_B R78_C R78_D: library part CMP-009-00693-3, "Chip Resistor, 1.50 KOhm, +/- 1%, 0.1 W, -55 to 155 degC, 0603 (1608 Metric)", Case/Package=0603, Max Operating Temperature=155°C, Min Operating Temperature=-55°C, Power=100mW, Tolerance=1%, Voltage Rating=75V
R79_A R79_B R79_C R79_D: library part CMP-009-00594-3, "Chip Resistor, 2.43 KOhm, +/- 1%, 0.1 W, -55 to 155 degC, 0603 (1608 Metric)", Case/Package=0603, Max Operating Temperature=155°C, Min Operating Temperature=-55°C, Power=100mW, Tolerance=1%, Voltage Rating=75V
R80_A R80_B R80_C R80_D: library part CMP-009-00691-3, "Chip Resistor, 3.48 KOhm, +/- 1%, 0.1 W, -55 to 155 degC, 0603 (1608 Metric)", Case/Package=0603, Max Operating Temperature=155°C, Min Operating Temperature=-55°C, Power=100mW, Tolerance=1%, Voltage Rating=75V
R81 R82 R85 R86: library part CMP-009-01213-6, "Chip Resistor, 3.3 Ohm, 1%, 0.5W, ±200ppm/°C, 1206 (3216 Metric)", Case/Package=1206, Manufacturer=Panasonic, Max Operating Temperature=155°C, Min Operating Temperature=-55°C, Power=500mW, Resistance=3R3, Tolerance=1%
R87_A R87_B R87_C R87_D R87_E R88_A R88_B R88_C R88_D R88_E: library part CMP-009-01065-2, "Chip Resistor, 100k Ohm, +/- 1%, 0.1 W, -55 to 155 degC, 0603 (1608 Metric)", Case/Package=0603, Max Operating Temperature=155°C, Min Operating Temperature=-55°C, Power=100mW, Tolerance=1%, Voltage Rating=75V
R89_A R89_B R89_C R89_D: library part CMP-009-01766-3, "Generic 1% 110 Ohm 0805 Resistor", Case/Package=0805, Max Operating Temperature=+155C, Min Operating Temperature=-55C, Power=0.125W, Tolerance=1%, Voltage Rating=150V
R90_A R90_B R90_C R90_D: library part CMP-009-01561-2, "Generic 1% 49.9 kOhm 0805 Resistor", Case/Package=0805, Max Operating Temperature=+155C, Min Operating Temperature=-55C, Power=0.125W, Tolerance=1%, Voltage Rating=150V
R91_A R91_B R91_C R91_D: library part CMP-009-01752-3, "Generic 1% 910 Ohm 0805 Resistor", Case/Package=0805, Max Operating Temperature=+155C, Min Operating Temperature=-55C, Power=0.125W, Tolerance=1%, Voltage Rating=150V
R94_A R94_B R94_C R94_D: library part CMP-009-01358-3, "Generic 1% 6.8 kOhm 0805 Resistor", Case/Package=0805, Max Operating Temperature=+155C, Min Operating Temperature=-55C, Power=0.125W, Tolerance=1%, Voltage Rating=150V
R95 R96 R97: library part CMP-009-00006-7, "Chip Resistor, 0 Ohm, 0.1 W, -55 to 155 degC, 0603 (1608 Metric)", Case/Package=0603, Max Operating Temperature=155°C, Min Operating Temperature=-55°C, Power=100mW, Tolerance=5%, Voltage Rating=50V
R98_A R98_B R98_C R98_D: library part CMP-009-01321-2, "Generic 1% 3.32 kOhm 0805 Resistor", Case/Package=0805, Max Operating Temperature=+155C, Min Operating Temperature=-55C, Power=0.125W, Tolerance=1%, Voltage Rating=150V
R99_A R99_B R99_C R99_D R100_A R100_B R100_C R100_D R101_A R101_B R101_C R101_D R103_A R103_B R103_C R103_D: library part CMP-009-01712-3, "Generic 1% 1 MOhm 0805 Resistor", Case/Package=0805, Max Operating Temperature=+155C, Min Operating Temperature=-55C, Power=0.125W, Tolerance=1%, Voltage Rating=150V
R102_A R102_B R102_C R102_D: library part CMP-009-02041-2, "5 mOhms 1% 2W Chip Current Sense Resistor Nonstandard Anti-Sulfur, Automotive AEC-Q200, Current Sense, Moisture Resistant, Pulse Withstanding Metal Element", Case/Package=2816, Max Operating Temperature=170, Max Power Dissipation=2W, Min Operating Temperature=-65, Temperature Coefficient=75ppm/°C, Tolerance=1%
R104_A R104_B R104_C R104_D: library part CMP-009-02043-1, "Res Thick Film 2010 220 Ohm 5% 3/4W ±100ppm/°C Molded SMD SMD Paper T/R", Case/Package=2010, Max Operating Temperature=155°C, Max Power Dissipation=750mW, Min Operating Temperature=-55°C, Temperature Coefficient=100ppm/°C, Tolerance=5%
TP1 TP2 TP3 TP4_A TP4_B TP4_C TP4_D: library part CMP-002-00083-13, "PC TEST POINT MINIATURE WHITE", Color=White, Manufacturer=Keystone, Max Operating Temperature=185°C, Min Operating Temperature=-40°C
TP5_A TP5_B TP5_C TP5_D: library part CMP-001-0002-14, "PC TEST POINT MINIATURE BLACK", Color=Black, Manufacturer=Keystone, Max Operating Temperature=185°C, Min Operating Temperature=-40°C
U1: library part CMP-010-00032-1, "Temp Sensor Analog 8-Pin SOIC N T/R", Case/Package=SOIC-8, Max Operating Temperature=150°C, Max Supply Voltage=30V, Min Operating Temperature=-55°C, Min Supply Voltage=4V
U2 U3_A U3_B U3_C U3_D U16_A U16_B U16_C U16_D: library part CMP-014-00006-4, "TLV2452A Dual 23-UA 220-KHZ Rail", Case/Package=D, Input Bias Current=5nA, Input Offset Voltage (Vos)=1mV, Max Dual Supply Voltage=3V, Max Operating Temperature=125°C, Max Power Dissipation=710mW, Max Supply Voltage=6V, Min Dual Supply Voltage=1.35V, Min Operating Temperature=-40°C, Min Supply Voltage=2.7V, Nominal Supply Current=84uA, Output Current=10mA, Voltage Gain=103dB
U4_A U4_B U4_C U4_D U4_E: library part CMP-010-00025-5, "Precision isolated bidirectional current sensor with Vsupply ratiometric reference 8-SOIC -40 to 125", Case/Package=SOIC, Current Sensing=5.6A, Frequency=80kHz, Max Operating Temperature=125°C, Max Supply Current=6mA, Min Operating Temperature=-40°C
U5: library part CMP-016-00018-2, "Automotive 5-V, 8: 1 1-channel general-purpose multiplexer 16-SOIC -40 to 125", Case/Package=SOIC, High Level Output Current=7.8mA, Max Operating Temperature=125°C, Max Supply Voltage=6V, Min Operating Temperature=-40°C, Min Supply Voltage=2V
U6_A U6_B U6_C U6_D: library part CMP-015-00012-3, "5.7kVrms 1.5A/2A single-channel opto-compatible isolated gate driver with 8 & 12V UVLO options", Case/Package=SOIC
U7_A U7_B U7_C U7_D U7_E: library part CMP-014-00043-5, "IC COMPARATOR RRI DUAL 8SOIC", Case/Package=SOIC-8, Input Bias Current=50pA, Input Offset Voltage (Vos)=5mV, Max Operating Temperature=125°C, Max Supply Current=40uA, Max Supply Voltage=5.5V, Min Operating Temperature=-40°C, Min Supply Voltage=2.7V
U8_A U8_B U8_C U8_D U8_E U21_A U21_B U21_C U21_D U22_A U22_B U22_C U22_D: library part CMP-016-00010-2, "Automotive single 1.65-V to 6.5-V buffer with Schmitt-Trigger inputs 5-SC70 -40 to 125", Case/Package=SOT-SC70, Max Operating Temperature=125°C, Max Supply Voltage=5.5V, Min Operating Temperature=-40°C, Min Supply Voltage=1.65V, Quiescent Current=20uA
U9_A U9_B U9_C U9_D U9_E U12_A U12_B U12_C U12_D U12_E: library part CMP-016-00017-2, "Inverter IC 3 Channel Schmitt Trigger SM8", Case/Package=SSOP, Max Operating Temperature=125°C, Max Supply Voltage=5.5V, Min Operating Temperature=-40°C, Min Supply Voltage=1.65V, Output Current=32mA
U10_A U10_B U10_C U10_D U10_E U13_A U13_B U13_C U13_D U13_E U14_A U14_B U14_C U14_D U14_E: library part CMP-016-00015-3, "Enhanced product single 3-input, 1.65-V to 5.5-V AND gate 6-SC70 -55 to 125", Case/Package=SC, Max Operating Temperature=125°C, Max Supply Voltage=5.5V, Min Operating Temperature=-55°C, Min Supply Voltage=1.65V, Quiescent Current=10uA
U11_A U11_B U11_C U11_D U11_E: library part CMP-016-00016-2, "Single D-Type Flip-Flop with Asynchronous Clear 6-SC70 -40 to 125", Case/Package=SC, Frequency=175MHz, Max Operating Temperature=125°C, Max Supply Voltage=5.5V, Min Operating Temperature=-40°C, Min Supply Voltage=1.65V, Output Current=32mA
U15_A U15_B U15_C U15_D: library part CMP-019-00076-3, "High input voltage regulator 5.0 V 3Ld SOT-223 3 SOT-223 TUBE RoHS Compliant: Yes", Case/Package=SOT-223-3, Dropout Voltage=1.2V, Max Input Voltage=55V, Max Operating Temperature=150C, Max Ouput Current=100mA, Min Input Voltage=6.2V, Min Operating Temperature=-40C
U17: library part CMP-019-00062-2, "0.5A DC/DC-Converter 'INNOLINE' SIP3 reg; V. In: 6.5-32; V. Out: 5.0; mA. Out: 500", Case/Package=SIP, Current - Output 1=500mA, Isolation Voltage=2kV, Max Input Voltage=32V, Max Operating Temperature=85°C, Max Output Power=2.5W, Max Output Voltage=5V, Max Power Dissipation=3W, Min Input Voltage=6.5V, Min Operating Temperature=-40°C, Nominal Input Voltage=24V, Switching Frequency=380kHz
U18_A U18_B U18_C U18_D: library part CMP-014-00037-3, "Current-sense amplifier 20V/V with latching comparator 8-VSSOP -40 to 125C, -4-V to 110-V, 1.3-MHz, ultra-precise.", Case/Package=VSSOP-8, Max Common Mode Voltage=110V, Max Input Voltage=20V, Max Operating Temperature=125C, Min Input Voltage=2.7V, Min Operating Temperature=-40C
U19: library part CMP-019-00064-2, "0.5A DC/DC-Converter 'INNOLINE' SIP3 reg; V. In: 15-32; V. Out: 12; mA. Out: 500", Case/Package=SIP, Current - Output 1=500mA, Isolation Voltage=1kV, Max Input Voltage=32V, Max Operating Temperature=85°C, Max Output Power=6W, Max Output Voltage=12V, Min Input Voltage=15V, Min Operating Temperature=-40°C, Nominal Input Voltage=24V, Switching Frequency=380kHz
U20_A U20_B U20_C U20_D U20_E: library part CMP-019-00065-5, "MAX6175 Series 5.005V ±0.1 % Surface Mount SeriesVoltage Reference - SOIC-8. V+T is Automotive Quality.", Case/Package=SOIC, Max Input Voltage=42V, Max Operating Temperature=125°C, Max Output Current=30mA, Min Operating Temperature=-40°C, Operating Supply Current=700uA, Output Voltage=5V, Temperature Coefficient=10ppm/°C, Tolerance=0.1%

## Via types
v1: diameter 30, hole 10, Top to Bottom, 873 vias

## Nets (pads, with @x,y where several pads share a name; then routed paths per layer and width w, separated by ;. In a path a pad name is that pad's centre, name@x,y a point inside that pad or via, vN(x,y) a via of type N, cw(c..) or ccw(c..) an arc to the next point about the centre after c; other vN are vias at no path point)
24V_UNSWCH_BUS_CURRENT_3: J3.18
ACTIVE-FAULT_A: R71_A.2 U8_A.4 U11_A.1 | length 541.2
  Top w10: U8_A.4@6495.59,1600.47 6600.47,1600.47 6735,1735 6830,1735 6850,1755 6850,1781.54 R71_A.2@6852.53,1784.06 ; R71_A.2@6852.53,1788 6852.94,1787.58 6877.42,1787.58 6905.79,1759.21 6928.15,1759.21 U11_A.1@6931.77,1755.59
ACTIVE-FAULT_B: R71_B.2 U8_B.4 U11_B.1 | length 480.8
  Top w10: U8_B.4@6495.59,4600.47 6600.47,4600.47 6710,4710 6780,4710 6800,4730 6800,4756.54 R71_B.2@6802.53,4759.06 ; R71_B.2@6802.52,4763 6802.94,4762.58 6827.42,4762.58 6855.79,4734.21 6878.15,4734.21 U11_B.1@6881.77,4730.59
ACTIVE-FAULT_C: R71_C.2 U8_C.4 U11_C.1 | length 480.8
  Top w10: U8_C.4@6470.59,7425.47 6575.47,7425.47 6685,7535 6755,7535 6775,7555 6775,7581.54 R71_C.2@6777.53,7584.06 ; R71_C.2@6777.53,7588 6777.94,7587.58 6802.42,7587.58 6830.79,7559.21 6853.15,7559.21 U11_C.1@6856.77,7555.59
ACTIVE-FAULT_D: R71_D.2 U8_D.4 U11_D.1 | length 480.8
  Top w10: U8_D.4@6495.59,10550.47 6600.47,10550.47 6710,10660 6780,10660 6800,10680 6800,10706.54 R71_D.2@6802.53,10709.06 ; R71_D.2@6802.53,10713 6802.94,10712.58 6827.42,10712.58 6855.79,10684.21 6878.15,10684.21 U11_D.1@6881.77,10680.59
ACTIVE-FAULT_E: R41.1 R71_E.2 TP1.1 U11_E.1 | length 555.9
  Top w10: R71_E.2@5027.53,11334.06 5056,11305.59 U11_E.1@5106.77,11305.59
  Top w15: TP1.1@4815,11455 R41.1@4815,11254.21 4899.21,11254.21 4930,11285 5010,11285 5025,11300 5025,11331.54 R71_E.2@5027.53,11334.06
BAYCAT_3V3_3: J2.18
BOARD_TEMP_1: C1.2 R1.1 R33.1 R36.1 | length 8870
  Top w10: C1.2@6575,6836.85 6576.66,6835.19 6604.81,6835.19 6630.58,6809.42 6653.02,6809.42 R1.1@6657.44,6805
  Top w15: v1(6490,6840) 6491.57,6838.43 6573.43,6838.43 C1.2@6575,6836.85
  L5 - Plane/Horiz w15: v1(2615,6825) 6470.94,6825 6485.94,6840 v1(6490,6840)
  Bottom w15: R36.1@2250,11360.63 R33.1@2450,11360.63 2454.92,11360.63 2471.04,11344.51 2471.04,11339.59 2615,11195.63 v1(2615,6825)
CGND: FB1.1 FB2.1
  other v1: 6390,100 6390,200 6390,300 6390,400 12300,500 12300,1200 13900,1700 13800,2200 12300,3500 12300,4200 13800,5200 12300,6500 12300,7200 13800,8200 12300,9250 12400,9800 6390.73,11597.2 6390.73,11697.2 6390.73,11797.2
CH-CNTLn_A: U12_A.5 U14_A.3 | length 841.4
  Top w10: v1(7005,1422) 7040.31,1422 U12_A.5@7041.61,1423.31 ; v1(7005,1656) 7010.41,1656 7026.41,1640 7087.43,1640 7115.18,1667.76 7149.82,1667.76 7167.57,1650 7207.57,1650 7212.57,1655 7307.57,1655 7327.57,1635 7475.11,1635 7502.87,1662.76 7502.87,1683.98 U14_A.3@7505.59,1686.69
  Bottom w10: v1(7005,1422) v1(7005,1656)
CH-CNTLn_B: U12_B.5 U14_B.3 | length 841.4
  Top w10: v1(6955,4397) 6990.31,4397 U12_B.5@6991.61,4398.31 ; v1(6955,4631) 6960.41,4631 6976.41,4615 7037.43,4615 7065.18,4642.76 7099.82,4642.76 7117.57,4625 7182.5,4625 7187.5,4630 7257.57,4630 7277.57,4610 7425.11,4610 7452.87,4637.76 7452.87,4658.98 U14_B.3@7455.59,4661.69
  Bottom w10: v1(6955,4397) v1(6955,4631)
CH-CNTLn_C: U12_C.5 U14_C.3 | length 806.8
  Top w10: v1(6930,7222) 6965.31,7222 U12_C.5@6966.61,7223.31 ; v1(6930,7445) 6971.42,7445 6976.42,7440 7090.06,7440 7094.15,7444.09 7237.17,7444.09 7241.26,7440 7413.06,7440 7430.59,7457.53 U14_C.3@7430.59,7486.69
  Bottom w10: v1(6930,7222) 6930,7225.25 6925,7230.25 6925,7382.66 6930,7387.66 v1(6930,7445)
CH-CNTLn_D: U12_D.5 U14_D.3 | length 828.1
  Top w10: v1(6955,10585) 6956.33,10585 6976.88,10564.45 7171.53,10564.45 7191.08,10584 7258.3,10584 7271.89,10570.41 7437.06,10570.41 7454.41,10587.76 7454.41,10608.98 U14_D.3@7457.13,10611.69 ; v1(6956.54,10359) 6957.29,10359 6969.29,10347 6989.29,10347 6990.6,10348.31 U12_D.5@6993.15,10348.31
  Bottom w10: v1(6955,10585) 6956.54,10583.46 6956.54,10520.28 6950,10513.74 6950,10368.78 6956.54,10362.25 v1(6956.54,10359)
CH-CNTLn_E: U12_E.5 U14_E.3 | length 836.2
  Top w10: v1(5180,10975) 5214.92,10975 U12_E.5@5216.61,10973.31 ; v1(5180,11206) 5183.25,11206 5204.13,11185.12 5323.1,11185.12 5337.98,11200 5461.56,11200 5476.45,11185.12 v1(5680,11185.12) ; v1@5680,11190 5680.3,11190.3 5680.3,11236.4 U14_E.3@5680.59,11236.69
  Bottom w10: v1(5180,10975) v1(5180,11206)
